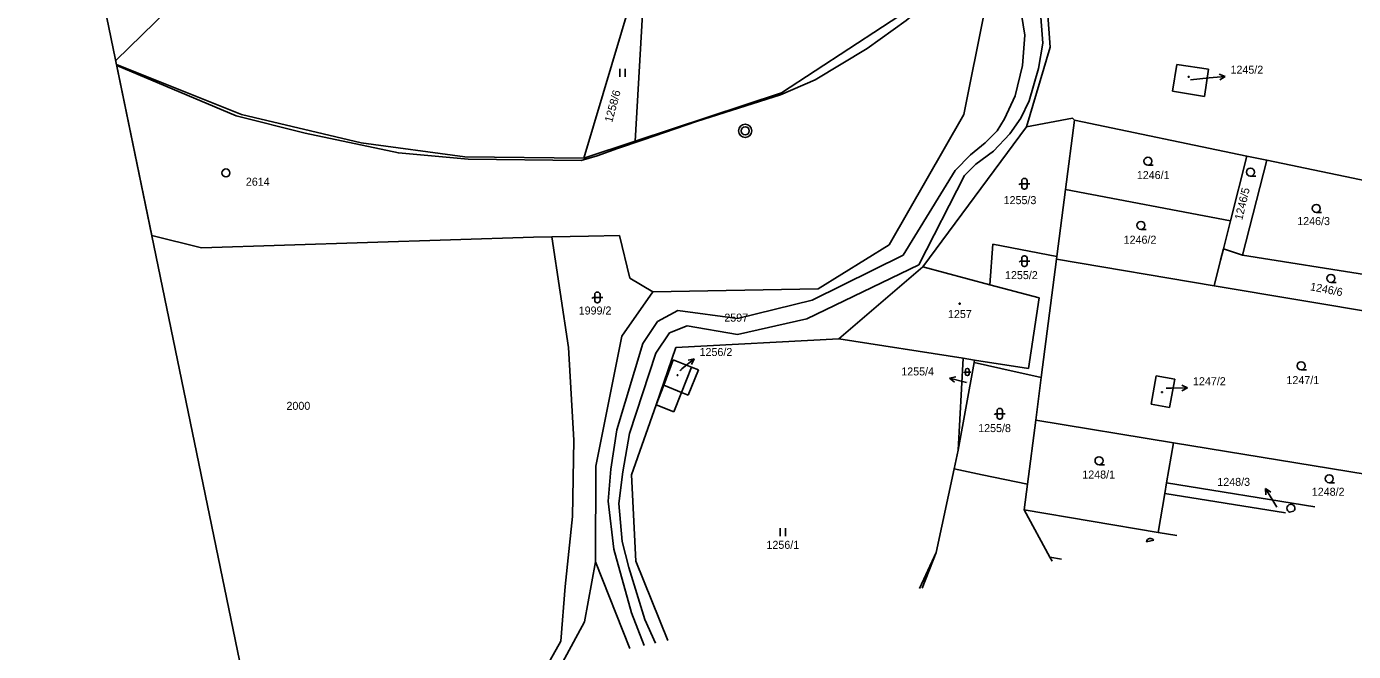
# Model space of a CAD drawing. Extents: x -804166 to -803706, y -1151030 to -1150147.
# Drawn here: x -804081.4 to -803832.6, y -1150810.4 to -1150693.3 of the extents above; entities that cross this region are included whole.
import ezdxf

# ---------------------------------------------------------------- set-up
doc = ezdxf.new("R2010")
doc.units = 0
for name, color, linetype in [('Default', 7, 'Continuous'), ('formát', 7, 'Continuous'), ('kilometráž - vrstava 7', 7, 'Continuous'), ('kn_celek - Cisla parcel pomocna', 7, 'Continuous'), ('kn_celek - Cisla pozemkovych parcel', 7, 'Continuous'), ('kn_celek - Cisla stavebnich parcel', 7, 'Continuous'), ('kn_celek - Hranice parcel', 7, 'Continuous'), ('kn_celek - Vnitrni kresby', 7, 'Continuous'), ('kn_celek - Znacky budov', 7, 'Continuous'), ('kn_celek - Znacky kultur', 7, 'Continuous'), ('plochy - SZDC', 7, 'Continuous'), ('PSR_C2_2_trasa_Vimperk - Kabelová trasa', 7, 'Continuous')]:
    doc.layers.add(name, color=color, linetype=linetype)

# ---------------------------------------------------------------- blocks, each defined once
blk = doc.blocks.new('304')
at = {"layer": 'Default'}
blk.add_line((-0.1, 0), (9.9, 0), dxfattribs=at)
blk.add_circle((-0.1, 7.5), 7.5, dxfattribs=at)
blk = doc.blocks.new('306')
at = {"layer": 'Default'}
for p, q in [((-5.2, 0), (-5.2, 15)), ((4.8, 0), (4.8, 15))]:
    blk.add_line(p, q, dxfattribs=at)
blk = doc.blocks.new('316')
at = {"layer": 'Default'}
for p, q in [((-8.3, 10), (-10, 8.1)), ((-5, 10), (-8.3, 10)), ((-5, 15.5), (-5, 4.5)), ((-5, 10), (5, 10)), ((0.5, 20), (-0.5, 20)), ((-0.5, 0), (0.5, 0)), ((5, 4.5), (5, 15.5)), ((10, 10), (5, 10))]:
    blk.add_line(p, q, dxfattribs=at)
for centre, start, end in [((-0.5, 15.5), 90, 180), ((-0.5, 4.5), 180, 270), ((0.5, 15.5), 0, 90), ((0.5, 4.5), 270, 0)]:
    blk.add_arc(centre, 4.5, start, end, dxfattribs=at)
blk = doc.blocks.new('402')
at = {"layer": 'Default'}
for p, q in [((-0.8, 0.8), (0.7, 0.8)), ((-0.8, 0.8), (-0.8, -0.7)), ((0.7, 0.8), (0.7, -0.7)), ((0.7, -0.7), (-0.8, -0.7))]:
    blk.add_line(p, q, dxfattribs=at)
blk = doc.blocks.new('Z61')
at = {"layer": 'Default'}
for p, q in [((0, 0), (30, 0)), ((30, 0), (19.2, 5.3)), ((30, 0), (19.2, -5.3))]:
    blk.add_line(p, q, dxfattribs=at)

msp = doc.modelspace()

# ---------------------------------------------------------------- linework, layer by layer
at = {"layer": 'Default'}
for p, q in [((-803844.59, -1150784.27), (-803843.84, -1150784.11)), ((-803871.43, -1150789.81), (-803870.08, -1150789.53))]:
    msp.add_line(p, q, dxfattribs=at)
for centre, start, end in [((-803844.35, -1150783.56), 312.5725, 250.7578), ((-803870.7, -1150789.95), 34.1452, 169.1851)]:
    msp.add_arc(centre, 0.75, start, end, dxfattribs=at)
at = {"layer": 'formát'}
msp.add_line((-804081.38, -1150618.72), (-803996.46, -1151030.05), dxfattribs=at)
at = {"layer": 'kilometráž - vrstava 7'}
for centre, radius in [((-803946.66, -1150712.87), 1.25), ((-803946.66, -1150712.87), 0.752), ((-804043.99, -1150720.76), 0.75)]:
    msp.add_circle(centre, radius, dxfattribs=at)
at = {"layer": 'kn_celek - Cisla parcel pomocna'}
for p, q in [((-803863.16, -1150703.33), (-803859.66, -1150702.97)), ((-803958.93, -1150757.79), (-803958.52, -1150757.45)), ((-803905.18, -1150759.97), (-803905.42, -1150759.91)), ((-803867.75, -1150761.07), (-803866.71, -1150761.05)), ((-803847.02, -1150783.33), (-803847.58, -1150782.42))]:
    msp.add_line(p, q, dxfattribs=at)
at = {"layer": 'kn_celek - Hranice parcel'}
for p, q in [((-804024.02, -1150660), (-804064.66, -1150699.72)), ((-803967.26, -1150714.81), (-803964.82, -1150671.1)), ((-803889.5, -1150697.18), (-803890.53, -1150682.77)), ((-803968.03, -1150688.27), (-803976.9, -1150717.98)), ((-803939.84, -1150705.78), (-803914.58, -1150689.29)), ((-803901.78, -1150690.55), (-803905.7, -1150709.82)), ((-803893.91, -1150712.15), (-803889.5, -1150697.18)), ((-804064.5, -1150700.47), (-804041.05, -1150709.83)), ((-803866.56, -1150705.44), (-803865.75, -1150700.44)), ((-803865.75, -1150700.44), (-803859.78, -1150701.34)), ((-803859.78, -1150701.34), (-803860.53, -1150706.41)), ((-803860.53, -1150706.41), (-803866.56, -1150705.44)), ((-803967.26, -1150714.81), (-803939.84, -1150705.78)), ((-804041.05, -1150709.83), (-804018.63, -1150715.09)), ((-803919.68, -1150734.23), (-803905.7, -1150709.82)), ((-803885.29, -1150710.51), (-803893.91, -1150712.15)), ((-803884.94, -1150710.9), (-803885.29, -1150710.51)), ((-803893.91, -1150712.15), (-803913.36, -1150738.33)), ((-803884.94, -1150710.9), (-803886.62, -1150723.87)), ((-803852.59, -1150717.62), (-803884.94, -1150710.9)), ((-804018.63, -1150715.09), (-803999.22, -1150717.72)), ((-803976.9, -1150717.98), (-803967.26, -1150714.81)), ((-803999.22, -1150717.72), (-803976.9, -1150717.98)), ((-803855.68, -1150729.74), (-803852.59, -1150717.62)), ((-803848.88, -1150718.39), (-803852.59, -1150717.62)), ((-803848.88, -1150718.39), (-803853.42, -1150736.14)), ((-803824.64, -1150723.42), (-803848.88, -1150718.39)), ((-803888.24, -1150736.39), (-803886.62, -1150723.87)), ((-803886.62, -1150723.87), (-803855.68, -1150729.74)), ((-803855.68, -1150729.74), (-803857.01, -1150734.98)), ((-804057.89, -1150732.49), (-804048.58, -1150734.81)), ((-804048.58, -1150734.81), (-803986.36, -1150732.8)), ((-803986.36, -1150732.8), (-803982.91, -1150732.74)), ((-803982.91, -1150732.74), (-803976.01, -1150732.6)), ((-803982.91, -1150732.74), (-803979.79, -1150753.43)), ((-803976.01, -1150732.6), (-803970.22, -1150732.49)), ((-803970.22, -1150732.49), (-803968.3, -1150740.45)), ((-803932.96, -1150742.47), (-803919.68, -1150734.23)), ((-803900.22, -1150734.12), (-803900.82, -1150741.68)), ((-803888.24, -1150736.39), (-803900.22, -1150734.12)), ((-803857.01, -1150734.98), (-803857.55, -1150737.1)), ((-803853.42, -1150736.14), (-803857.01, -1150734.98)), ((-803891.15, -1150759.06), (-803888.31, -1150736.91)), ((-803888.31, -1150736.91), (-803888.24, -1150736.39)), ((-803858.77, -1150741.88), (-803888.31, -1150736.91)), ((-803857.55, -1150737.1), (-803858.77, -1150741.88)), ((-803853.42, -1150736.14), (-803828.98, -1150740)), ((-803968.3, -1150740.45), (-803963.98, -1150743)), ((-803913.36, -1150738.33), (-803929.09, -1150751.85)), ((-803913.36, -1150738.33), (-803900.82, -1150741.68)), ((-803963.98, -1150743), (-803932.96, -1150742.47)), ((-803900.82, -1150741.68), (-803891.56, -1150744.16)), ((-803858.77, -1150741.88), (-803806.45, -1150750.68)), ((-803969.76, -1150751.35), (-803963.98, -1150743)), ((-803891.56, -1150744.16), (-803893.55, -1150757.36)), ((-803974.64, -1150775.65), (-803969.76, -1150751.35)), ((-803929.09, -1150751.85), (-803959.63, -1150753.44)), ((-803905.82, -1150755.46), (-803929.09, -1150751.85)), ((-803979.79, -1150753.43), (-803978.76, -1150770.8)), ((-803963.36, -1150764.17), (-803959.63, -1150753.44)), ((-803961.94, -1150760.53), (-803960.13, -1150755.78)), ((-803956.75, -1150757.12), (-803960.13, -1150755.78)), ((-803957.33, -1150762.4), (-803955.38, -1150757.63)), ((-803955.38, -1150757.63), (-803956.75, -1150757.12)), ((-803905.82, -1150755.46), (-803906.72, -1150772.7)), ((-803906.72, -1150772.7), (-803903.76, -1150756.28)), ((-803903.65, -1150755.79), (-803905.82, -1150755.46)), ((-803903.65, -1150755.79), (-803903.76, -1150756.28)), ((-803903.76, -1150756.28), (-803898.73, -1150757.39)), ((-803903.65, -1150755.79), (-803893.55, -1150757.36)), ((-803898.73, -1150757.39), (-803891.15, -1150759.06)), ((-803891.15, -1150759.06), (-803892.17, -1150767.03)), ((-803869.59, -1150758.74), (-803870.58, -1150764.06)), ((-803869.59, -1150758.74), (-803866.12, -1150759.37)), ((-803867.11, -1150764.7), (-803866.12, -1150759.37)), ((-803961.94, -1150760.53), (-803963.36, -1150764.17)), ((-803960.05, -1150765.5), (-803958.59, -1150761.86)), ((-803958.59, -1150761.86), (-803957.33, -1150762.4)), ((-803963.36, -1150764.17), (-803967.94, -1150777.28)), ((-803963.36, -1150764.17), (-803960.05, -1150765.5)), ((-803867.11, -1150764.7), (-803870.58, -1150764.06)), ((-803893.74, -1150779.06), (-803892.17, -1150767.03)), ((-803892.17, -1150767.03), (-803866.39, -1150771.27)), ((-803978.76, -1150770.8), (-803979, -1150785.08)), ((-803906.72, -1150772.7), (-803907.47, -1150776.18)), ((-803866.39, -1150771.27), (-803867.66, -1150778.8)), ((-803866.39, -1150771.27), (-803819.23, -1150779.03)), ((-803974.75, -1150793.56), (-803974.64, -1150775.65)), ((-803967.94, -1150777.28), (-803967.18, -1150793.48)), ((-803907.47, -1150776.18), (-803910.85, -1150791.83)), ((-803902.21, -1150777.28), (-803907.47, -1150776.18)), ((-803893.74, -1150779.06), (-803902.21, -1150777.28)), ((-803894.37, -1150783.87), (-803893.74, -1150779.06)), ((-803867.66, -1150778.8), (-803867.98, -1150780.76)), ((-803867.66, -1150778.8), (-803839.89, -1150783.3)), ((-803867.98, -1150780.76), (-803869.21, -1150788.06)), ((-803845.36, -1150784.43), (-803867.98, -1150780.76)), ((-803979, -1150785.08), (-803980.38, -1150798.23)), ((-803869.21, -1150788.06), (-803894.37, -1150783.87)), ((-803894.37, -1150783.87), (-803889.52, -1150792.72)), ((-803869.21, -1150788.06), (-803865.75, -1150788.64)), ((-803910.85, -1150791.83), (-803914, -1150798.6)), ((-803910.85, -1150791.83), (-803913.5, -1150798.49)), ((-803974.75, -1150793.56), (-803976.77, -1150804.82)), ((-803968.31, -1150809.81), (-803974.75, -1150793.56)), ((-803967.18, -1150793.48), (-803961.19, -1150808.34)), ((-803889.52, -1150792.72), (-803889.12, -1150793.46)), ((-803887.35, -1150793.09), (-803889.52, -1150792.72)), ((-803980.38, -1150798.23), (-803981.21, -1150808.47)), ((-803976.77, -1150804.82), (-803980.93, -1150812.42)), ((-803981.21, -1150808.47), (-803983.75, -1150813))]:
    msp.add_line(p, q, dxfattribs=at)
at = {"layer": 'kn_celek - Vnitrni kresby'}
for p, q in [((-803895.2, -1150689.12), (-803894.23, -1150694.97)), ((-803890.85, -1150696.47), (-803891.41, -1150689.12)), ((-803894.23, -1150694.97), (-803894.66, -1150700.65)), ((-803891.66, -1150701.2), (-803890.85, -1150696.47)), ((-803894.66, -1150700.65), (-803896.07, -1150706.33)), ((-803893.43, -1150707.23), (-803891.66, -1150701.2)), ((-803896.07, -1150706.33), (-803898.03, -1150710.64)), ((-803894.98, -1150710.47), (-803893.43, -1150707.23)), ((-803897.05, -1150713.46), (-803894.98, -1150710.47)), ((-803899.43, -1150712.88), (-803901.67, -1150715.12)), ((-803898.03, -1150710.64), (-803899.43, -1150712.88)), ((-803901.67, -1150715.12), (-803904.42, -1150717.36)), ((-803900.12, -1150716.68), (-803897.05, -1150713.46)), ((-803904.42, -1150717.36), (-803907.28, -1150720.31)), ((-803903.41, -1150719.1), (-803900.12, -1150716.68)), ((-803907.28, -1150720.31), (-803917.05, -1150736.14)), ((-803905.57, -1150721.21), (-803903.41, -1150719.1)), ((-803914.13, -1150737.98), (-803905.57, -1150721.21)), ((-803934.13, -1150744.6), (-803917.05, -1150736.14)), ((-803935.11, -1150748.1), (-803914.13, -1150737.98)), ((-803948.11, -1150747.99), (-803934.13, -1150744.6)), ((-803959.26, -1150746.54), (-803963.09, -1150748.6)), ((-803948.11, -1150747.99), (-803959.26, -1150746.54)), ((-803963.09, -1150748.6), (-803965.86, -1150752.7)), ((-803960.85, -1150750.71), (-803957.52, -1150749.38)), ((-803957.52, -1150749.38), (-803948.1, -1150751.02)), ((-803948.1, -1150751.02), (-803935.11, -1150748.1)), ((-803965.86, -1150752.7), (-803970.71, -1150768.87)), ((-803963.4, -1150754.51), (-803960.85, -1150750.71)), ((-803968.32, -1150769.58), (-803963.4, -1150754.51)), ((-803958.59, -1150761.86), (-803956.75, -1150757.12)), ((-803961.94, -1150760.53), (-803958.59, -1150761.86)), ((-803970.71, -1150768.87), (-803971.82, -1150776.26)), ((-803969.58, -1150776.73), (-803968.32, -1150769.58)), ((-803971.82, -1150776.26), (-803972.33, -1150782.24)), ((-803970.33, -1150782.63), (-803969.58, -1150776.73)), ((-803972.33, -1150782.24), (-803971.3, -1150791.24)), ((-803969.74, -1150789.75), (-803970.33, -1150782.63)), ((-803968.47, -1150794.64), (-803969.74, -1150789.75)), ((-803968, -1150803.14), (-803971.3, -1150791.24)), ((-803968.47, -1150794.64), (-803965.47, -1150804.37)), ((-803965.62, -1150809.25), (-803968, -1150803.14)), ((-803965.47, -1150804.37), (-803963.47, -1150808.81))]:
    msp.add_line(p, q, dxfattribs=at)
at = {"layer": 'plochy - SZDC'}
for p, q in [((-803914.58, -1150689.29), (-803939.84, -1150705.78)), ((-803905.7, -1150709.82), (-803901.78, -1150690.55)), ((-804041.05, -1150709.83), (-804064.5, -1150700.47)), ((-804064.5, -1150700.47), (-804057.89, -1150732.49)), ((-803939.84, -1150705.78), (-803967.26, -1150714.81)), ((-804018.63, -1150715.09), (-804041.05, -1150709.83)), ((-803919.68, -1150734.23), (-803905.7, -1150709.82)), ((-803999.22, -1150717.72), (-804018.63, -1150715.09)), ((-803967.26, -1150714.81), (-803976.9, -1150717.98)), ((-803976.9, -1150717.98), (-803999.22, -1150717.72)), ((-804057.89, -1150732.49), (-804048.58, -1150734.81)), ((-804048.58, -1150734.81), (-803986.36, -1150732.8)), ((-803986.36, -1150732.8), (-803982.91, -1150732.74)), ((-803982.91, -1150732.74), (-803976.01, -1150732.6)), ((-803976.01, -1150732.6), (-803970.22, -1150732.49)), ((-803970.22, -1150732.49), (-803968.3, -1150740.45)), ((-803932.96, -1150742.47), (-803919.68, -1150734.23)), ((-803968.3, -1150740.45), (-803963.98, -1150743)), ((-803963.98, -1150743), (-803932.96, -1150742.47))]:
    msp.add_line(p, q, dxfattribs=at)
at = {"layer": 'PSR_C2_2_trasa_Vimperk - Kabelová trasa'}
msp.add_line((-803965.8, -1150714.54), (-803955.77, -1150711.14), dxfattribs=at)
for points in [[(-803940.06, -1150706.11), (-803933.55, -1150703.31), (-803923.82, -1150697.47), (-803916.47, -1150692.18), (-803905.7, -1150683.2), (-803894.81, -1150671.7), (-803893.85, -1150661.82)], [(-804064.46, -1150700.65), (-804042.05, -1150710.07), (-804029.14, -1150713.3), (-804011.66, -1150716.99), (-803998.6, -1150718.16), (-803977.42, -1150718.41), (-803974.41, -1150717.57), (-803970.61, -1150716.16), (-803965.8, -1150714.54)], [(-803955.77, -1150711.14), (-803947.91, -1150708.63), (-803940.06, -1150706.11)]]:
    msp.add_lwpolyline(points, dxfattribs=at)

# ---------------------------------------------------------------- block references
at = {"layer": 'kn_celek - Cisla parcel pomocna'}
for p, xscale, yscale, rotation in [((-803859.66, -1150702.97), 0.09999999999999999, 0.1, 5.815620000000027), ((-803958.52, -1150757.45), 0.1, 0.09999999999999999, 39.597660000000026), ((-803905.42, -1150759.91), 0.1, 0.09999999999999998, 165.92084999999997), ((-803866.71, -1150761.05), 0.1, 0.09999999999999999, 0.8508600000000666), ((-803847.58, -1150782.42), 0.1, 0.10000000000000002, 121.54293)]:
    msp.add_blockref('Z61', p, dxfattribs=dict(at, xscale=xscale, yscale=yscale, rotation=rotation))
at = {"layer": 'kn_celek - Znacky budov', "xscale": 0.1, "yscale": 0.10000000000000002}
for p in [(-803863.51, -1150702.78), (-803906.44, -1150745.25), (-803959.34, -1150758.63), (-803868.52, -1150761.8)]:
    msp.add_blockref('402', p, dxfattribs=at)
at = {"layer": 'kn_celek - Znacky kultur'}
for name, p, xscale, yscale in [('306', (-803969.64, -1150702.76), 0.1, 0.10000000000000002), ('304', (-803871.15, -1150719.31), 0.1, 0.10000000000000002), ('304', (-803851.93, -1150721.36), 0.1, 0.10000000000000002), ('316', (-803894.32, -1150723.77), 0.1, 0.10000000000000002), ('304', (-803839.6, -1150728.16), 0.1, 0.10000000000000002), ('304', (-803872.47, -1150731.33), 0.1, 0.10000000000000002), ('316', (-803894.31, -1150738.28), 0.1, 0.10000000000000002), ('304', (-803836.86, -1150741.26), 0.1, 0.10000000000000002), ('316', (-803974.37, -1150745.07), 0.1, 0.10000000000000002), ('316', (-803905.02, -1150758.71), 0.067, 0.067), ('304', (-803842.43, -1150757.62), 0.1, 0.10000000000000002), ('316', (-803898.94, -1150766.86), 0.1, 0.10000000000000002), ('304', (-803880.32, -1150775.4), 0.1, 0.10000000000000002), ('304', (-803837.17, -1150778.77), 0.1, 0.10000000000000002), ('306', (-803939.6, -1150788.79), 0.1, 0.10000000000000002)]:
    msp.add_blockref(name, p, dxfattribs=dict(at, xscale=xscale, yscale=yscale))

# ---------------------------------------------------------------- texts
at = {"layer": 'kn_celek - Cisla parcel pomocna'}
for s, p in [('1245/2', (-803855.68, -1150702.17)), ('1256/2', (-803955.21, -1150755.04)), ('1255/4', (-803917.4, -1150758.68)), ('1247/2', (-803862.71, -1150760.51)), ('1248/3', (-803858.15, -1150779.36))]:
    msp.add_text(s, height=1.5, dxfattribs=at).set_placement(p)
at = {"layer": 'kn_celek - Cisla pozemkovych parcel'}
for s, height, rotation, p in [('1258/6', 1.5, 74.7, (-803971.6, -1150711.4)), ('1246/5', 1.5, 76.5, (-803853.48, -1150729.68)), ('1246/6', 1.5, 349.2, (-803840.84, -1150742.71)), ('1248/3', 0.1, 350.1, (-803847.01, -1150783.3))]:
    msp.add_text(s, height=height, rotation=rotation, dxfattribs=at).set_placement(p)
for s, height, p in [('1246/1', 1.5, (-803873.24, -1150721.9)), ('2614', 1.5, (-804040.26, -1150723.15)), ('1255/3', 1.5, (-803898.21, -1150726.6)), ('1246/3', 1.5, (-803843.17, -1150730.52)), ('1246/2', 1.5, (-803875.71, -1150734.01)), ('1255/2', 1.5, (-803897.95, -1150740.64)), ('1999/2', 1.5, (-803977.87, -1150747.27)), ('2597', 1.5, (-803950.57, -1150748.6)), ('1255/4', 0.1, (-803905.45, -1150759.94)), ('1247/1', 1.5, (-803845.19, -1150760.3)), ('2000', 1.5, (-804032.65, -1150765.12)), ('1255/8', 1.5, (-803902.98, -1150769.29)), ('1248/1', 1.5, (-803883.46, -1150777.99)), ('1248/2', 1.5, (-803840.44, -1150781.21)), ('1256/1', 1.5, (-803942.67, -1150791.15))]:
    msp.add_text(s, height=height, dxfattribs=at).set_placement(p)
at = {"layer": 'kn_celek - Cisla stavebnich parcel'}
for s, height, p in [('1245/2', 0.1, (-803863.16, -1150703.3)), ('1257', 1.5, (-803908.64, -1150747.93)), ('1256/2', 0.1, (-803958.93, -1150757.76)), ('1247/2', 0.1, (-803867.75, -1150761.04))]:
    msp.add_text(s, height=height, dxfattribs=at).set_placement(p)

doc.saveas('drawing.dxf')
